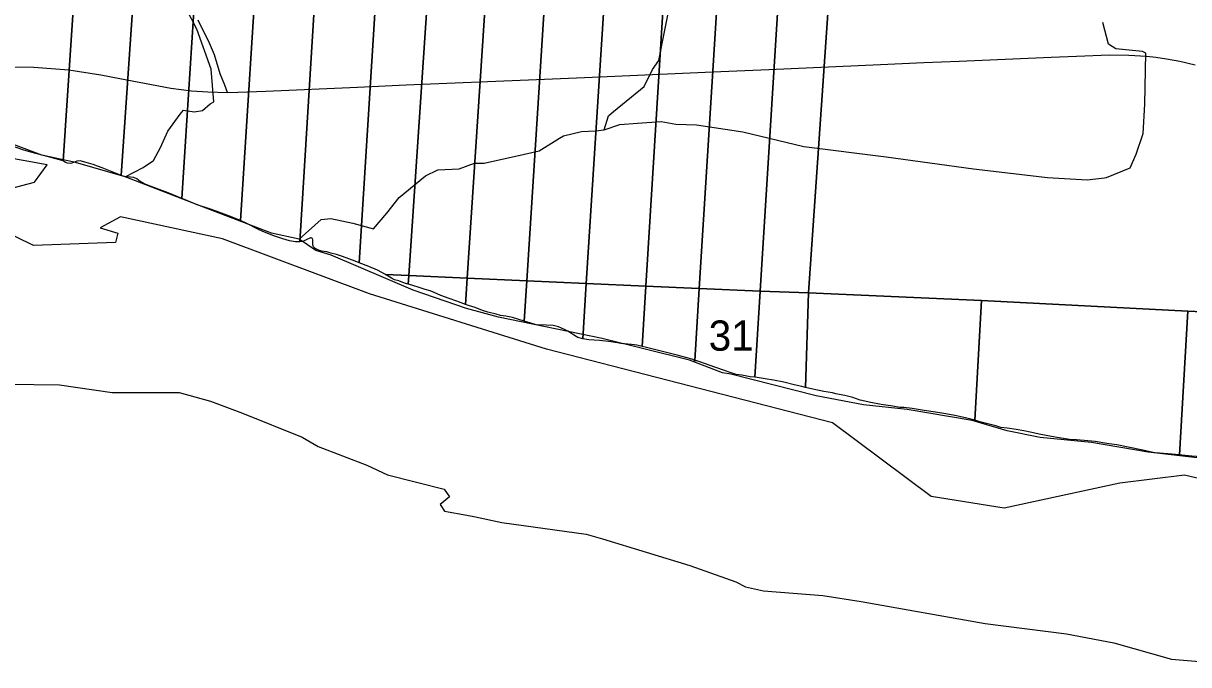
# Model space of a CAD drawing. Extents: x 1878108 to 2183446, y 146837 to 508383.
# Drawn here: x 2040993 to 2049515, y 214326 to 219015 of the extents above; entities that cross this region are included whole.
import ezdxf

# ---------------------------------------------------------------- set-up
doc = ezdxf.new("R2010")
doc.units = 0
for name, color, linetype in [('GM_X_County', 7, 'Continuous'), ('GM_X_County_Road', 7, 'Continuous'), ('GM_X_Major_River', 7, 'Continuous'), ('GM_X_Minor_River', 7, 'Continuous'), ('GM_X_Section', 7, 'Continuous'), ('GM_X_Section_Text', 7, 'Continuous'), ('GM_X_State_Route', 7, 'Continuous'), ('GM_X_Township', 7, 'Continuous')]:
    doc.layers.add(name, color=color, linetype=linetype)

msp = doc.modelspace()

# ---------------------------------------------------------------- linework, layer by layer
at = {"layer": 'GM_X_County'}
for points in [[(2040546.9, 217716.1), (2041075.7, 217853.1), (2041167.8, 217981.1), (2040086.3, 218174.8)], [(2050043.5, 215579.1), (2049485.7, 215711.7), (2049012.4, 215653), (2048164.8, 215471.3), (2047631.2, 215554.9), (2046910, 216093.3), (2044819.4, 216632.3), (2043524.2, 217037), (2042449.3, 217438.4), (2041705.1, 217600.7), (2041554.4, 217520.9), (2041684.1, 217480.2), (2041666.2, 217411.7), (2041068.1, 217391.3), (2040557.3, 217639.7)]]:
    msp.add_lwpolyline(points, dxfattribs=at)
at = {"layer": 'GM_X_County_Road'}
msp.add_lwpolyline([(2042487.5, 218510.2), (2042466.2, 218563.8), (2042433.9, 218644.9), (2042392.5, 218785.8), (2042355.8, 218871), (2042271.7, 219039.1)], dxfattribs=at)
at = {"layer": 'GM_X_Major_River'}
for points in [[(2049681.8, 215826.4), (2049219.4, 215879.9), (2048805.1, 215951.5), (2048428.8, 215987), (2048188.6, 216034.8), (2047932.4, 216110.6), (2047456, 216192.1), (2047137.7, 216225.7), (2046791.4, 216291.3), (2046166.9, 216450.7), (2046106.8, 216460.7), (2045864.5, 216552.5), (2045226, 216709.9), (2044469.3, 216867.1), (2044233.1, 216930.9), (2043844.7, 217064.6), (2043244, 217320.2), (2043131.9, 217354.1), (2043011.7, 217436), (2042807.6, 217479.8), (2042311, 217671.5), (2041738.4, 217893), (2041374.1, 217998.7), (2041129.9, 218050.4), (2040771.5, 218184.2)], [(2040881.6, 216377.5), (2041257.8, 216372), (2041644.2, 216316.4), (2042132.5, 216317.1), (2042362.7, 216253.3), (2042594.9, 216165.5), (2043031.4, 215989.8), (2043149.6, 215921.8), (2043505.9, 215786.1), (2043656.1, 215714.2), (2044070.5, 215608.6), (2044108.6, 215552.5), (2044042.6, 215498.4), (2044072.7, 215448.3), (2044236.8, 215418.5), (2044300.9, 215406.6), (2044493, 215364.8), (2045109.5, 215279.4), (2045227.6, 215247.5), (2045868.3, 215052.1), (2046204.6, 214932.4), (2046274.7, 214894.4), (2046404.8, 214866.5), (2046839.1, 214831), (2047119.4, 214787.3), (2048028.1, 214626.3), (2048622.6, 214550.9), (2048968.9, 214485.3), (2049389.3, 214367.7), (2049883.6, 214326.3)]]:
    msp.add_lwpolyline(points, dxfattribs=at)
at = {"layer": 'GM_X_Minor_River'}
for points in [[(2041738.4, 217893), (2041868.7, 217960.7), (2041944.5, 218013.1), (2041996.3, 218107.5), (2042050.1, 218226), (2042139.8, 218350.6), (2042165.7, 218380.8), (2042243.6, 218366.9), (2042303.5, 218377.1), (2042359.3, 218425.4), (2042387.2, 218441.5), (2042367.1, 218680.2), (2042263, 218972.9), (2042185, 219123.3)], [(2043011.7, 217436), (2043170.4, 217580.4), (2043242.3, 217588.6), (2043404, 217552.9), (2043553.7, 217513.1), (2043651.4, 217627.7), (2043741.1, 217742.2), (2043934.6, 217899.2), (2044024.4, 217943.5), (2044180.1, 217951.9), (2044291.8, 217992.3), (2044363.6, 217992.5), (2044659, 218059.4), (2044764.7, 218083.7), (2044914.4, 218176.3), (2044942.3, 218192.4), (2045076, 218224.9), (2045177.8, 218229.1), (2045241.7, 218237.3), (2045271.5, 218339.7), (2045309.4, 218369.9), (2045532.8, 218553), (2045594.5, 218677.5), (2045640.4, 218743.8), (2045676.2, 218928.5), (2045706, 219075.1)], [(2045240.4, 218237.1), (2045355.4, 218275.7), (2045485.1, 218284), (2045656.8, 218298.4), (2045764.6, 218278.6), (2045916.3, 218272.9), (2046255.6, 218221.5), (2046700.8, 218114.2), (2047303.7, 218039.3), (2047942.5, 217952.4), (2048483.4, 217887.4), (2048772.9, 217870), (2048898.6, 217884.4), (2048914.6, 217888.4), (2049088.1, 217959), (2049132, 218059.5), (2049181.7, 218210.1), (2049195.5, 218424.8), (2049201.2, 218796.1), (2049177.2, 218810.1), (2048983.6, 218829.7), (2048929.6, 218863.7), (2048887.6, 219022.1)]]:
    msp.add_lwpolyline(points, dxfattribs=at)
at = {"layer": 'GM_X_Section'}
for points in [[(2040585.3, 222757.3), (2041597.7, 222717.4), (2041283.7, 218009), (2041231.7, 218024.9), (2041141.6, 218048.6), (2041049.5, 218074.3), (2040989.4, 218090), (2040881.2, 218129.7), (2040837.1, 218145.5), (2040809.1, 218153.5), (2040783.1, 218155.4), (2040761.1, 218163.3), (2040689, 218185), (2040618.9, 218202.8), (2040572.8, 218214.6), (2040506.7, 218228.4), (2040422.7, 218248.1), (2040368.6, 218253.9), (2040285.5, 218259.9)], [(2042038.7, 222698.3), (2041709.8, 217901.6), (2041654.1, 217924.3), (2041570, 217958), (2041536, 217971.9), (2041503.9, 217983.8), (2041451.8, 217997.7), (2041409.8, 218009.5), (2041385.8, 218007.4), (2041359.8, 217997.3), (2041339.8, 217991.3), (2041315.8, 217993.2), (2041301.8, 217997.1), (2041283.7, 218009), (2041597.7, 222717.4)], [(2042469.9, 222679.1), (2042152.8, 217734.4), (2042052.8, 217775.7), (2041966.7, 217807.4), (2041876.5, 217841.1), (2041848.4, 217859), (2041824.3, 217878.9), (2041802.3, 217888.8), (2041778.3, 217890.8), (2041744.3, 217892.6), (2041722.3, 217896.6), (2041709.8, 217901.6), (2042038.7, 222698.3)], [(2042906.7, 222659.7), (2042580.8, 217573), (2042557.6, 217583.4), (2042501.5, 217605.2), (2042403.4, 217642.9), (2042355.3, 217658.7), (2042265.2, 217688.4), (2042173, 217726.1), (2042152.8, 217734.4), (2042469.9, 222679.1)], [(2043338, 222640.5), (2043014.3, 217417.2), (2042984.3, 217418.8), (2042940.3, 217424.7), (2042890.2, 217438.5), (2042826.1, 217460.3), (2042746, 217492), (2042707.9, 217509.9), (2042623.7, 217553.6), (2042580.8, 217573), (2042906.7, 222659.7)], [(2043785.6, 222620.6), (2043449, 217265.2), (2043420.9, 217276.3), (2043326.8, 217310), (2043284.7, 217323.8), (2043242.7, 217333.7), (2043212.6, 217343.6), (2043172.6, 217349.5), (2043146.6, 217359.4), (2043124.5, 217371.3), (2043114.5, 217381.3), (2043110.4, 217395.3), (2043110.3, 217431.3), (2043108.3, 217441.3), (2043104.2, 217445.2), (2043098.2, 217447.2), (2043092.2, 217447.2), (2043066.3, 217435.1), (2043038.3, 217421), (2043014.3, 217417.2), (2043338, 222640.5)], [(2044178.1, 222603.1), (2043811.9, 217171.8), (2043642, 217179.3), (2043583.2, 217210.9), (2043521.1, 217236.6), (2043449, 217265.2), (2043785.6, 222620.6)], [(2044596.8, 222584.5), (2044239.7, 217152.7), (2043811.9, 217171.8), (2044178.1, 222603.1)], [(2045022.4, 222565.6), (2044675.8, 217133.2), (2044239.7, 217152.7), (2044596.8, 222584.5)], [(2045036.3, 222564.9), (2045457.6, 222546.2), (2045110.1, 217113.9), (2044675.8, 217133.2), (2045022.4, 222565.6)], [(2045880.8, 222527.4), (2045546.5, 217094.4), (2045110.1, 217113.9), (2045457.6, 222546.2)], [(2046277.3, 222509.7), (2045936.1, 217077.1), (2045546.5, 217094.4), (2045880.8, 222527.4)], [(2046720.8, 222490), (2046382.1, 217057.2), (2045936.1, 217077.1), (2046277.3, 222509.7)], [(2047110.2, 222472.7), (2046735.7, 217044.1), (2046382.1, 217057.2), (2046720.8, 222490)], [(2047690.1, 222439.9), (2048301.3, 222416), (2048929.5, 222390.1), (2049522.3, 222362.5), (2050127.6, 222334.2), (2050697.8, 222313.3), (2051296.4, 222289.1), (2051925.1, 222262.3), (2052522.2, 222232.5), (2052508, 221908.8), (2052253.7, 216795.4), (2050863.1, 216849.2), (2049508.1, 216911.7), (2047999, 216988.8), (2046735.7, 217044.1), (2047110.2, 222472.7)], [(2043811.9, 217171.8), (2043807, 217107.5), (2043779.6, 217115.5), (2043739.5, 217131.4), (2043707.6, 217139.2), (2043685.5, 217151.2), (2043642, 217179.3)], [(2044239.7, 217152.7), (2044227.1, 216960.6), (2044164.2, 216982.8), (2044108.1, 217002.6), (2044046, 217024.4), (2043997.9, 217046.2), (2043967.9, 217058.2), (2043931.8, 217070), (2043895.8, 217081.9), (2043833.7, 217099.7), (2043807, 217107.5), (2043811.9, 217171.8)], [(2044675.8, 217133.2), (2044656.9, 216836.9), (2044570.7, 216864.2), (2044520.7, 216874), (2044482.6, 216879.9), (2044450.6, 216887.8), (2044390.5, 216903.6), (2044350.5, 216915.4), (2044296.4, 216937.3), (2044248.3, 216953.1), (2044227.1, 216960.6), (2044239.7, 217152.7)], [(2045110.1, 217113.9), (2045084.1, 216708), (2045047.4, 216717.8), (2045035.4, 216725.8), (2044975.2, 216763.6), (2044951.1, 216777.5), (2044907.1, 216795.4), (2044867, 216805.2), (2044817, 216809), (2044745, 216810.8), (2044728.9, 216814.8), (2044704.9, 216822.7), (2044656.9, 216836.9), (2044675.8, 217133.2)], [(2045546.5, 217094.4), (2045519.3, 216652.5), (2045479.7, 216661.3), (2045439.7, 216667.2), (2045363.6, 216674.9), (2045337.6, 216678.8), (2045271.5, 216688.6), (2045207.5, 216696.4), (2045127.5, 216700.1), (2045084.1, 216708), (2045110.1, 217113.9)], [(2045936.1, 217077.1), (2045902.9, 216548.5), (2045888.2, 216556.7), (2045864.1, 216564.6), (2045774.1, 216588.3), (2045687.9, 216610), (2045607.8, 216629.8), (2045541.8, 216647.5), (2045519.3, 216652.5), (2045546.5, 217094.4)], [(2046382.1, 217057.2), (2046342.9, 216427.5), (2046308.8, 216430.2), (2046248.7, 216441.9), (2046206.7, 216447.8), (2046170.6, 216459.7), (2046112.5, 216479.5), (2046008.4, 216517.1), (2045948.3, 216538.9), (2045918.2, 216546.8), (2045902.9, 216548.5), (2045936.1, 217077.1)], [(2046735.7, 217044.1), (2046714.2, 216353), (2046687.2, 216358.8), (2046629.1, 216371.2), (2046555, 216391), (2046478.9, 216406.7), (2046418.8, 216416.5), (2046358.8, 216426.3), (2046342.9, 216427.5), (2046382.1, 217057.2)], [(2046735.7, 217044.1), (2047999, 216988.8), (2047950.7, 216113.4), (2047884.3, 216131.6), (2047806.2, 216147.3), (2047740.1, 216159.1), (2047664.1, 216172.8), (2047582, 216184.5), (2047493.9, 216198.2), (2047431.9, 216206), (2047403.9, 216205.9), (2047351.8, 216215.7), (2047265.7, 216229.4), (2047189.7, 216243.2), (2047113.6, 216260.9), (2047059.5, 216278.7), (2047001.4, 216294.5), (2046959.4, 216302.4), (2046935.4, 216306.3), (2046911.3, 216314.2), (2046847.3, 216324), (2046767.2, 216341.7), (2046714.2, 216353)], [(2047999, 216988.8), (2049508.1, 216911.7), (2049448.8, 215860.6), (2049361.6, 215868.6), (2049269.6, 215874.3), (2049243.6, 215880.2), (2049179.5, 215894), (2049071.4, 215917.6), (2048989.3, 215933.4), (2048917.2, 215943.1), (2048831.2, 215956.8), (2048751.1, 215964.6), (2048695.1, 215970.4), (2048643.1, 215972.2), (2048615, 215978.1), (2048567, 215985.9), (2048511, 215993.7), (2048432.9, 216009.5), (2048354.8, 216025.2), (2048310.8, 216035), (2048254.7, 216044.8), (2048186.6, 216056.6), (2048142.6, 216060.5), (2048104.6, 216072.3), (2048046.5, 216086.1), (2047988.4, 216101.9), (2047950.7, 216113.4)], [(2049508.1, 216911.7), (2050863.1, 216849.2), (2050771.2, 215763.7), (2050738.4, 215767.4), (2050642.4, 215777.1), (2050534.4, 215774.7), (2050440.3, 215776.4), (2050380.3, 215778.2), (2050340.3, 215784), (2050288.2, 215785.9), (2050224.2, 215797.7), (2050156.1, 215809.4), (2050112.1, 215813.2), (2050064, 215817.1), (2050012, 215820.9), (2049908, 215820.6), (2049830, 215822.3), (2049769.9, 215830.1), (2049681.9, 215833.8), (2049609.8, 215839.5), (2049571.8, 215847.4), (2049537.8, 215851.3), (2049465.7, 215859), (2049448.8, 215860.6)]]:
    msp.add_lwpolyline(points, close=True, dxfattribs=at)
at = {"layer": 'GM_X_State_Route'}
msp.add_lwpolyline([(2040856.8, 218697), (2041069.8, 218693.6), (2041325.7, 218674.5), (2041560.1, 218638.9), (2041699.8, 218611.7), (2042071.6, 218540.7), (2042223.2, 218521.7), (2042342.8, 218513.4), (2042487.5, 218510.2), (2042562.3, 218511.3), (2042767.6, 218520.3), (2043438.1, 218548.1), (2043791.8, 218564.9), (2044745.8, 218603.9), (2045096.1, 218618.4), (2046035.6, 218659.7), (2046445, 218677.6), (2047261.7, 218714.4), (2047578.6, 218727.8), (2047836.3, 218738.9), (2048510.2, 218766.8), (2048695.4, 218774.6), (2048935.3, 218783.6), (2049077, 218782.4), (2049206.4, 218774.6), (2049274.5, 218766.8), (2049352.6, 218755.7), (2049449.7, 218737.8), (2049563.5, 218711)], dxfattribs=at)
at = {"layer": 'GM_X_Township'}
for points in [[(2040546.9, 217716.1), (2041075.7, 217853.1), (2041167.8, 217981.1), (2040086.3, 218174.8)], [(2050043.5, 215579.1), (2049485.7, 215711.7), (2049012.4, 215653), (2048164.8, 215471.3), (2047631.2, 215554.9), (2046910, 216093.3), (2044819.4, 216632.3), (2043524.2, 217037), (2042449.3, 217438.4), (2041705.1, 217600.7), (2041554.4, 217520.9), (2041684.1, 217480.2), (2041666.2, 217411.7), (2041068.1, 217391.3), (2040557.3, 217639.7)]]:
    msp.add_lwpolyline(points, dxfattribs=at)

# ---------------------------------------------------------------- texts
at = {"layer": 'GM_X_Section_Text'}
msp.add_text('31', height=221, rotation=0.00001, dxfattribs=at).set_placement((2046005.3, 216621.7))

doc.saveas('drawing.dxf')
